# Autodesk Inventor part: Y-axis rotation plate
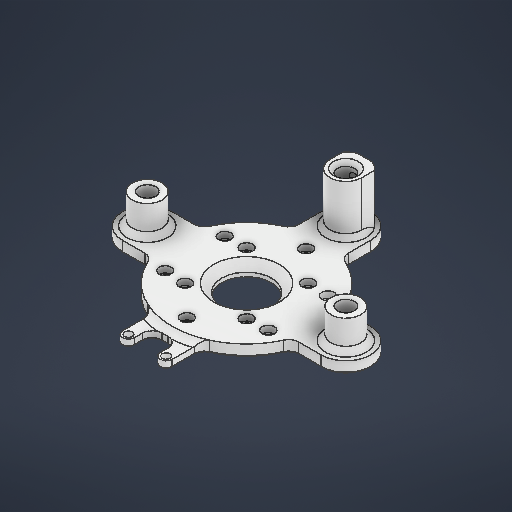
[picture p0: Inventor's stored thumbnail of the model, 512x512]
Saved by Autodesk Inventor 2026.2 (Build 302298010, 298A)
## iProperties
Created: 2026-04
Part Number: Y-axis rotation plate
Material: PBT 플라스틱
Document SubType Name: Modeling
Designer: work
Density: 1.31 g/cm^3
Appearance: 매끄러움 - 흰색
Author: work
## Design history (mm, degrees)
sketch "스케치1" dims "d28" = 6
  geometry: L1 (-15.5, 15.5)-(15.5, 15.5); L2 (15.5, 15.5)-(15.5, -15.5); L3 (15.5, -15.5)-(-15.5, -15.5); L4 (-15.5, -15.5)-(-15.5, 15.5); L5 (-15.5, 15.5)-(15.5, -15.5); L6 (15.5, 15.5)-(-15.5, -15.5); L7 (0, 0)-(50, 0); L8 (0, 0)-(0, -50); L9 (0, 0)-(-50, 0); L10 (35.355, 12.5)-(50, 12.5); L11 (35.355, -12.5)-(50, -12.5); L12 (12.5, 35.355)-(12.5, 50); L13 (-12.5, 35.355)-(-12.5, 50); L14 (-35.355, 12.5)-(-50, 12.5); L15 (-35.355, -12.5)-(-50, -12.5); L16 (-12.5, -35.355)-(-12.5, -50); L17 (12.5, -35.355)-(12.5, -50); L18 (6.5, 50)-(6.5, 41); L19 (6.5, 41)-(-6.5, 41); L20 (-6.5, 41)-(-6.5, 50); L21 (12.5, 50)-(12.5, 35.355); L22 (-12.5, 50)-(-12.5, 35.355); C1 r 12.5 at (0, 0); C2 r 4.25 at (50, 0); C3 r 4.25 at (0, -50); C4 r 4.25 at (-50, 0); C5 r 2 at (15.5, 15.5); C6 r 2 at (-15.5, 15.5); C7 r 2 at (-15.5, -15.5); C8 r 2 at (15.5, -15.5); C9 r 2 at (0, -30); C10 r 2 at (25.981, -15); C11 r 2 at (25.981, 15); C12 r 2 at (0, 30); C13 r 2 at (-25.981, 15); C14 r 2 at (-25.981, -15); C15 r 2 at (9.5, 50); C16 r 2 at (-9.5, 50); A1 r 37.5 centre (0, 0) between (35.355, 12.5) and (35.355, -12.5); A2 r 12.5 centre (50, 0) between (50, -12.5) and (50, 12.5); A3 r 12.5 centre (0, 50) between (12.5, 50) and (-12.5, 50); A4 r 12.5 centre (-50, 0) between (-50, 12.5) and (-50, -12.5); A5 r 12.5 centre (0, -50) between (-12.5, -50) and (12.5, -50); A6 r 3 centre (9.5, 50) between (12.5, 50) and (6.5, 50); 13 further points
  constraints: 44 end point, 22 centre point, 12 point on circle, 11 coincident, 5 perpendicular, 4 equal length, 4 horizontal, 3 midpoint, 3 tangent, 1 concentric, 1 point on line, 1 vertical, 53 other
  dimensions: "d0" = 31 distance of L2.end L3.end; "d1" = 31 distance of L1.end L2.end; "d2" = 25 diameter of C1; "d3" = 50 distance of L7.start L7.end; "d4" = 50 distance of L7.start L8.end; "d5" = 8.5 diameter of C2; "d6" = 8.5 diameter of C3; "d7" = 50 distance of L7.start L9.end; "d8" = 8.5 diameter of C4; "d9" = 4 diameter of C5; "d10" = 4 diameter of C6; "d11" = 4 diameter of C7; "d12" = 4 diameter of C8; "d13" = 4 diameter of C9; "d14" = 30 distance of L7.start C9.centre; "d17" = 360 deg dimension on L7.start C9.centre (derived); "d19" = 75 diameter of A1; "d20" = 25 distance from line of point (42.678, 12.5) L11; "d23" = 360 deg dimension on L7.start A2.centre (derived); "d26" = 4 diameter of C15; "d27" = 4 diameter of C16
  node "스케치 - 원형 패턴1" dims "d17" = 360 deg (derived)
  node "스케치 - 원형 패턴2" dims "d23" = 360 deg (derived)
extrude "돌출1" new body sketch "스케치1" distance "d30" = 6; taper "d31" = 0 deg
extrude "돌출2" join sketch "스케치1" distance "d32" = 4; taper "d33" = 0 deg
extrude "돌출3" join sketch "스케치1" distance "d34" = 2; taper "d35" = 0 deg
sketch "스케치2"
  geometry: L1 (35.355, -12.5)-(50, -12.5) reference; L2 (50, 12.5)-(35.355, 12.5) reference; L3 (12.5, 35.355)-(12.5, 50) reference; L4 (-12.5, 50)-(-12.5, 35.355) reference; L5 (-35.355, 12.5)-(-50, 12.5) reference; L6 (-50, -12.5)-(-35.355, -12.5) reference; C1 r 4.25 at (-50, 0) reference; C2 r 4.25 at (50, 0) reference; C3 r 4.25 at (0, 50) reference; C4 r 2 at (25.981, 15) reference; C5 r 2 at (25.981, -15) reference; C6 r 2 at (0, -30) reference; C7 r 2 at (-25.981, -15) reference; C8 r 2 at (-25.981, 15) reference; C9 r 2 at (0, 30) reference; C10 r 2 at (-15.5, 15.5) reference; C11 r 2 at (15.5, 15.5) reference; C12 r 2 at (15.5, -15.5) reference; C13 r 2 at (-15.5, -15.5) reference; C14 r 12.5 at (0, 0) reference; C15 r 6.25 at (50, 0); A1 r 12.5 centre (50, 0) between (50, -12.5) and (50, 12.5) reference; A2 r 37.5 centre (0, 0) between (35.355, 12.5) and (12.5, 35.355) reference; A3 r 12.5 centre (0, 50) between (12.5, 50) and (-12.5, 50) reference; A4 r 37.5 centre (0, 0) between (-12.5, 35.355) and (-35.355, 12.5) reference; A5 r 12.5 centre (-50, 0) between (-50, 12.5) and (-50, -12.5) reference; A6 r 37.5 centre (0, 0) between (-35.355, -12.5) and (35.355, -12.5) reference; 1 further point
  constraints: 1 centre point, 1 coincident
  dimensions: "d36" = 2 radial gap between concentric circles of C15 C2
extrude "돌출4" join sketch "스케치2" distance "d37" = 4; taper "d38" = 0 deg
chamfer "모따기1" distance "d39" = 4; stored, may be unused: second distance "d40" = 2, angle "d41" = 45 deg
sketch "스케치4"
  geometry: L1 (35.355, -12.5)-(50, -12.5) reference; L2 (50, 12.5)-(35.355, 12.5) reference; L3 (12.5, 35.355)-(12.5, 50) reference; L4 (-12.5, 50)-(-12.5, 35.355) reference; L5 (-35.355, 12.5)-(-50, 12.5) reference; L6 (-50, -12.5)-(-35.355, -12.5) reference; C1 r 10.25 at (0, 50) reference; C2 r 2 at (-15.5, -15.5) reference; C3 r 2 at (15.5, -15.5) reference; C4 r 2 at (15.5, 15.5) reference; C5 r 2 at (-15.5, 15.5) reference; C6 r 2 at (0, 30) reference; C7 r 2 at (-25.981, 15) reference; C8 r 2 at (-25.981, -15) reference; C9 r 2 at (0, -30) reference; C10 r 2 at (25.981, -15) reference; C11 r 2 at (25.981, 15) reference; C12 r 10.25 at (50, 0) reference; C13 r 10.25 at (-50, 0) reference; A1 r 12.5 centre (50, 0) between (50, -12.5) and (50, 12.5) reference; A2 r 37.5 centre (0, 0) between (35.355, 12.5) and (12.5, 35.355) reference; A3 r 12.5 centre (0, 50) between (12.5, 50) and (-12.5, 50) reference; A4 r 37.5 centre (0, 0) between (-12.5, 35.355) and (-35.355, 12.5) reference; A5 r 12.5 centre (-50, 0) between (-50, 12.5) and (-50, -12.5) reference; A6 r 37.5 centre (0, 0) between (-35.355, -12.5) and (35.355, -12.5) reference; 11 further points
  constraints: 10 coincident
hole "구멍2" sketch "스케치4" at (0, 30), (15.5, 15.5), (25.981, 15), (15.5, -15.5), (25.981, -15), (0, -30), (-15.5, -15.5), (-15.5, 15.5), (-25.981, 15), (-25.981, -15) diameter "d52" = 4; stored, may be unused: countersink angle "d56" = 90 deg, drill point angle "d58" = 118 deg; dims "d53" = 6, "d54" = 6.2, "d55" = 3.2, "d57" = 8
fillet "모깎기1" dims "d59" = 5
chamfer "모따기2" distance "d60" = 1; stored, may be unused: second distance "d61" = 2, angle "d62" = 45 deg
sketch "스케치5"
  geometry: L1 (38.73, -12.5)-(50, -12.5) reference; L2 (50, 12.5)-(38.73, 12.5) reference; L3 (12.5, 38.73)-(12.5, 50) reference; L4 (-12.5, 50)-(-12.5, 38.73) reference; L5 (-38.73, 12.5)-(-50, 12.5) reference; L6 (-50, -12.5)-(-38.73, -12.5) reference; L7 (-8, 50)-(8, 50); L8 (8, 50)-(8, 59.605); L9 (8, 59.605)-(-8, 59.605); L10 (-8, 59.605)-(-8, 50); C1 r 3.1 at (-25.981, -15) reference; C2 r 3.1 at (-25.981, 15) reference; C3 r 3.1 at (-15.5, 15.5) reference; C4 r 3.1 at (-15.5, -15.5) reference; C5 r 3.1 at (0, -30) reference; C6 r 3.1 at (25.981, -15) reference; C7 r 3.1 at (15.5, -15.5) reference; C8 r 3.1 at (25.981, 15) reference; C9 r 3.1 at (15.5, 15.5) reference; C10 r 3.1 at (0, 30) reference; C11 r 10.25 at (-50, 0) reference; C12 r 10.25 at (50, 0) reference; C13 r 10.25 at (0, 50) reference; C14 r 16.5 at (0, 0) reference; C15 r 4.25 at (0, 50) reference; A1 r 12.5 centre (50, 0) between (50, -12.5) and (50, 12.5) reference; A2 r 5 centre (38.73, 17.5) between (34.173, 15.441) and (38.73, 12.5) reference; A3 r 37.5 centre (0, 0) between (34.173, 15.441) and (15.441, 34.173) reference; A4 r 5 centre (17.5, 38.73) between (12.5, 38.73) and (15.441, 34.173) reference; A5 r 12.5 centre (0, 50) between (12.5, 50) and (-12.5, 50) reference; A6 r 5 centre (-17.5, 38.73) between (-15.441, 34.173) and (-12.5, 38.73) reference; A7 r 37.5 centre (0, 0) between (-15.441, 34.173) and (-34.173, 15.441) reference; A8 r 5 centre (-38.73, 17.5) between (-38.73, 12.5) and (-34.173, 15.441) reference; A9 r 12.5 centre (-50, 0) between (-50, 12.5) and (-50, -12.5) reference; A10 r 5 centre (-38.73, -17.5) between (-34.173, -15.441) and (-38.73, -12.5) reference; A11 r 37.5 centre (0, 0) between (-34.173, -15.441) and (-15.441, -34.173) reference; A12 r 37.5 centre (0, 0) between (-15.441, -34.173) and (15.441, -34.173) reference; A13 r 37.5 centre (0, 0) between (15.441, -34.173) and (34.173, -15.441) reference; A14 r 5 centre (38.73, -17.5) between (38.73, -12.5) and (34.173, -15.441) reference; A15 r 8 centre (0, 50) between (-8, 50) and (8, 50); 5 further points
  constraints: 8 end point, 3 point on circle, 2 parallel, 1 centre point, 1 coincident, 1 horizontal, 1 perpendicular
  dimensions: "d63" = 16 diameter of A15; "d68" = 16 distance of L7.start L7.end
extrude "돌출5" join sketch "스케치5" distance "d64" = 25; taper "d65" = 0 deg
sketch "스케치6"
  geometry: L1 (-0.671, 0)-(7.829, 0) reference; L2 (3.579, 0)-(3.579, -18); C1 r 2 at (3.579, -6); C2 r 2 at (3.579, -18); 1 further point
  constraints: 2 centre point, 2 end point, 1 coincident, 1 midpoint, 1 point on line, 1 vertical
  dimensions: "d69" = 4 diameter of C1; "d70" = 4 diameter of C2; "d71" = 12 distance of L2.end C1.centre; "d72" = 6 distance from line of L1 C1.centre
extrude "돌출6" cut sketch "스케치6" stored distance "d73" = 25; taper "d74" = 0 deg
chamfer "모따기3" distance "d75" = 2; stored, may be unused: second distance "d76" = 2, angle "d77" = 45 deg
sketch "스케치7"
  geometry: L1 (38.73, -12.5)-(50, -12.5) reference; L2 (50, 12.5)-(38.73, 12.5) reference; L3 (12.5, 38.73)-(12.5, 50) reference; L4 (-12.5, 50)-(-12.5, 38.73) reference; L5 (-38.73, 12.5)-(-50, 12.5) reference; L6 (-50, -12.5)-(-38.73, -12.5) reference; C1 r 3.1 at (-25.981, -15) reference; C2 r 3.1 at (-25.981, 15) reference; C3 r 3.1 at (-15.5, 15.5) reference; C4 r 3.1 at (-15.5, -15.5) reference; C5 r 3.1 at (0, -30) reference; C6 r 3.1 at (25.981, -15) reference; C7 r 3.1 at (15.5, -15.5) reference; C8 r 3.1 at (25.981, 15) reference; C9 r 3.1 at (15.5, 15.5) reference; C10 r 3.1 at (0, 30) reference; C11 r 10.25 at (-50, 0) reference; C12 r 10.25 at (50, 0) reference; C13 r 16.5 at (0, 0) reference; C14 r 7.5 at (50, 0); C15 r 7.5 at (-50, 0); C16 r 4.25 at (50, 0) reference; C17 r 4.25 at (50, 0) reference; C18 r 4.25 at (-50, 0) reference; C19 r 4.25 at (-50, 0) reference; A1 r 12.5 centre (50, 0) between (50, -12.5) and (50, 12.5) reference; A2 r 5 centre (38.73, 17.5) between (34.173, 15.441) and (38.73, 12.5) reference; A3 r 37.5 centre (0, 0) between (34.173, 15.441) and (15.441, 34.173) reference; A4 r 5 centre (17.5, 38.73) between (12.5, 38.73) and (15.441, 34.173) reference; A5 r 12.5 centre (0, 50) between (12.5, 50) and (-12.5, 50) reference; A6 r 5 centre (-17.5, 38.73) between (-15.441, 34.173) and (-12.5, 38.73) reference; A7 r 37.5 centre (0, 0) between (-15.441, 34.173) and (-34.173, 15.441) reference; A8 r 5 centre (-38.73, 17.5) between (-38.73, 12.5) and (-34.173, 15.441) reference; A9 r 12.5 centre (-50, 0) between (-50, 12.5) and (-50, -12.5) reference; A10 r 5 centre (-38.73, -17.5) between (-34.173, -15.441) and (-38.73, -12.5) reference; A11 r 37.5 centre (0, 0) between (-34.173, -15.441) and (-15.441, -34.173) reference; A12 r 37.5 centre (0, 0) between (-15.441, -34.173) and (15.441, -34.173) reference; A13 r 37.5 centre (0, 0) between (15.441, -34.173) and (34.173, -15.441) reference; A14 r 5 centre (38.73, -17.5) between (38.73, -12.5) and (34.173, -15.441) reference; A15 r 10.25 centre (0, 50) between (3.579, 59.605) and (-3.579, 59.605) reference; A16 r 10.25 centre (0, 50) between (8, 56.408) and (3.579, 59.605) reference; A17 r 10.25 centre (0, 50) between (-8, 56.408) and (8, 56.408) reference; A18 r 10.25 centre (0, 50) between (-3.579, 59.605) and (-8, 56.408) reference; 1 further point
  constraints: 2 centre point, 2 coincident
  dimensions: "d78" = 15 diameter of C14; "d79" = 15 diameter of C15
extrude "돌출7" join sketch "스케치7" distance "d80" = 15; taper "d81" = 0 deg
node "솔리드1"
pattern_circular "원형 패턴1" dims angle "d43" = 360 deg
node "투영된 루프1"
node "투영된 루프2"
node "투영된 루프3"
node "투영된 루프4"
node "투영된 루프5"
node "투영된 루프6"
node "투영된 루프7"
feature "A9D066F2-1C7D-4E18-AEED-F7BC21143FA4" dims "d52" = 4, "d53" = 6, "d54" = 6.2, "d55" = 3.2, "d56" = 90 deg, "d57" = 8, "d58" = 118 deg
